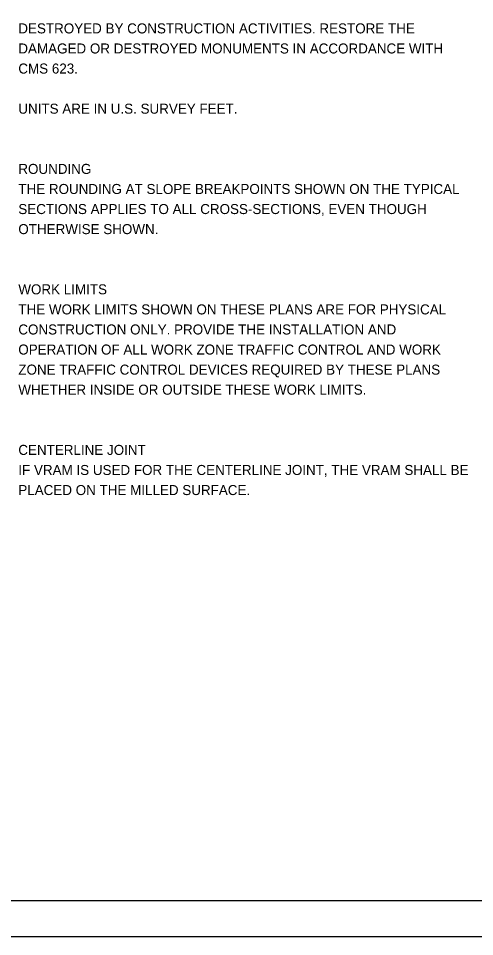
# Model space of a CAD drawing. Extents: x -28.8 to 41.7, y 0 to 25.4.
# Drawn here: x 17.24 to 23.61, y 0 to 12.81 of the extents above; entities that cross this region are included whole.
import ezdxf

# ---------------------------------------------------------------- set-up
doc = ezdxf.new("R2010")
doc.units = 0
for name, color, linetype in [('SH_Border', 7, 'Continuous'), ('SH_Cut_Line', 7, 'Continuous'), ('SH_Text', 7, 'Continuous')]:
    doc.layers.add(name, color=color, linetype=linetype)

msp = doc.modelspace()

# ---------------------------------------------------------------- linework, layer by layer
at = {"layer": 'SH_Border'}
msp.add_lwpolyline([(1.5, 21.5), (33.5, 21.5), (33.5, 0.5), (1.5, 0.5)], close=True, dxfattribs=at)
at = {"layer": 'SH_Cut_Line'}
msp.add_lwpolyline([(0, 0), (34, 0), (34, 22), (0, 22)], close=True, dxfattribs=at)

# ---------------------------------------------------------------- texts
at = {"layer": 'SH_Text'}
for s, p in [('DESTROYED BY CONSTRUCTION ACTIVITIES. RESTORE THE', (17.24, 12.6)), ('DAMAGED OR DESTROYED MONUMENTS IN ACCORDANCE WITH', (17.24, 12.32)), ('CMS 623.', (17.24, 12.04)), ('UNITS ARE IN U.S. SURVEY FEET.', (17.24, 11.48)), ('ROUNDING', (17.24, 10.64)), ('THE ROUNDING AT SLOPE BREAKPOINTS SHOWN ON THE TYPICAL', (17.24, 10.36)), ('SECTIONS APPLIES TO ALL CROSS-SECTIONS, EVEN THOUGH', (17.24, 10.08)), ('OTHERWISE SHOWN.', (17.24, 9.8)), ('WORK LIMITS', (17.24, 8.96)), ('THE WORK LIMITS SHOWN ON THESE PLANS ARE FOR PHYSICAL', (17.24, 8.68)), ('CONSTRUCTION ONLY. PROVIDE THE INSTALLATION AND', (17.24, 8.4)), ('OPERATION OF ALL WORK ZONE TRAFFIC CONTROL AND WORK', (17.24, 8.12)), ('ZONE TRAFFIC CONTROL DEVICES REQUIRED BY THESE PLANS', (17.24, 7.84)), ('WHETHER INSIDE OR OUTSIDE THESE WORK LIMITS.', (17.24, 7.56)), ('CENTERLINE JOINT', (17.24, 6.72)), ('IF VRAM IS USED FOR THE CENTERLINE JOINT, THE VRAM SHALL BE', (17.24, 6.44)), ('PLACED ON THE MILLED SURFACE.', (17.24, 6.16))]:
    msp.add_text(s, height=0.14, dxfattribs=at).set_placement(p)

doc.saveas('drawing.dxf')
